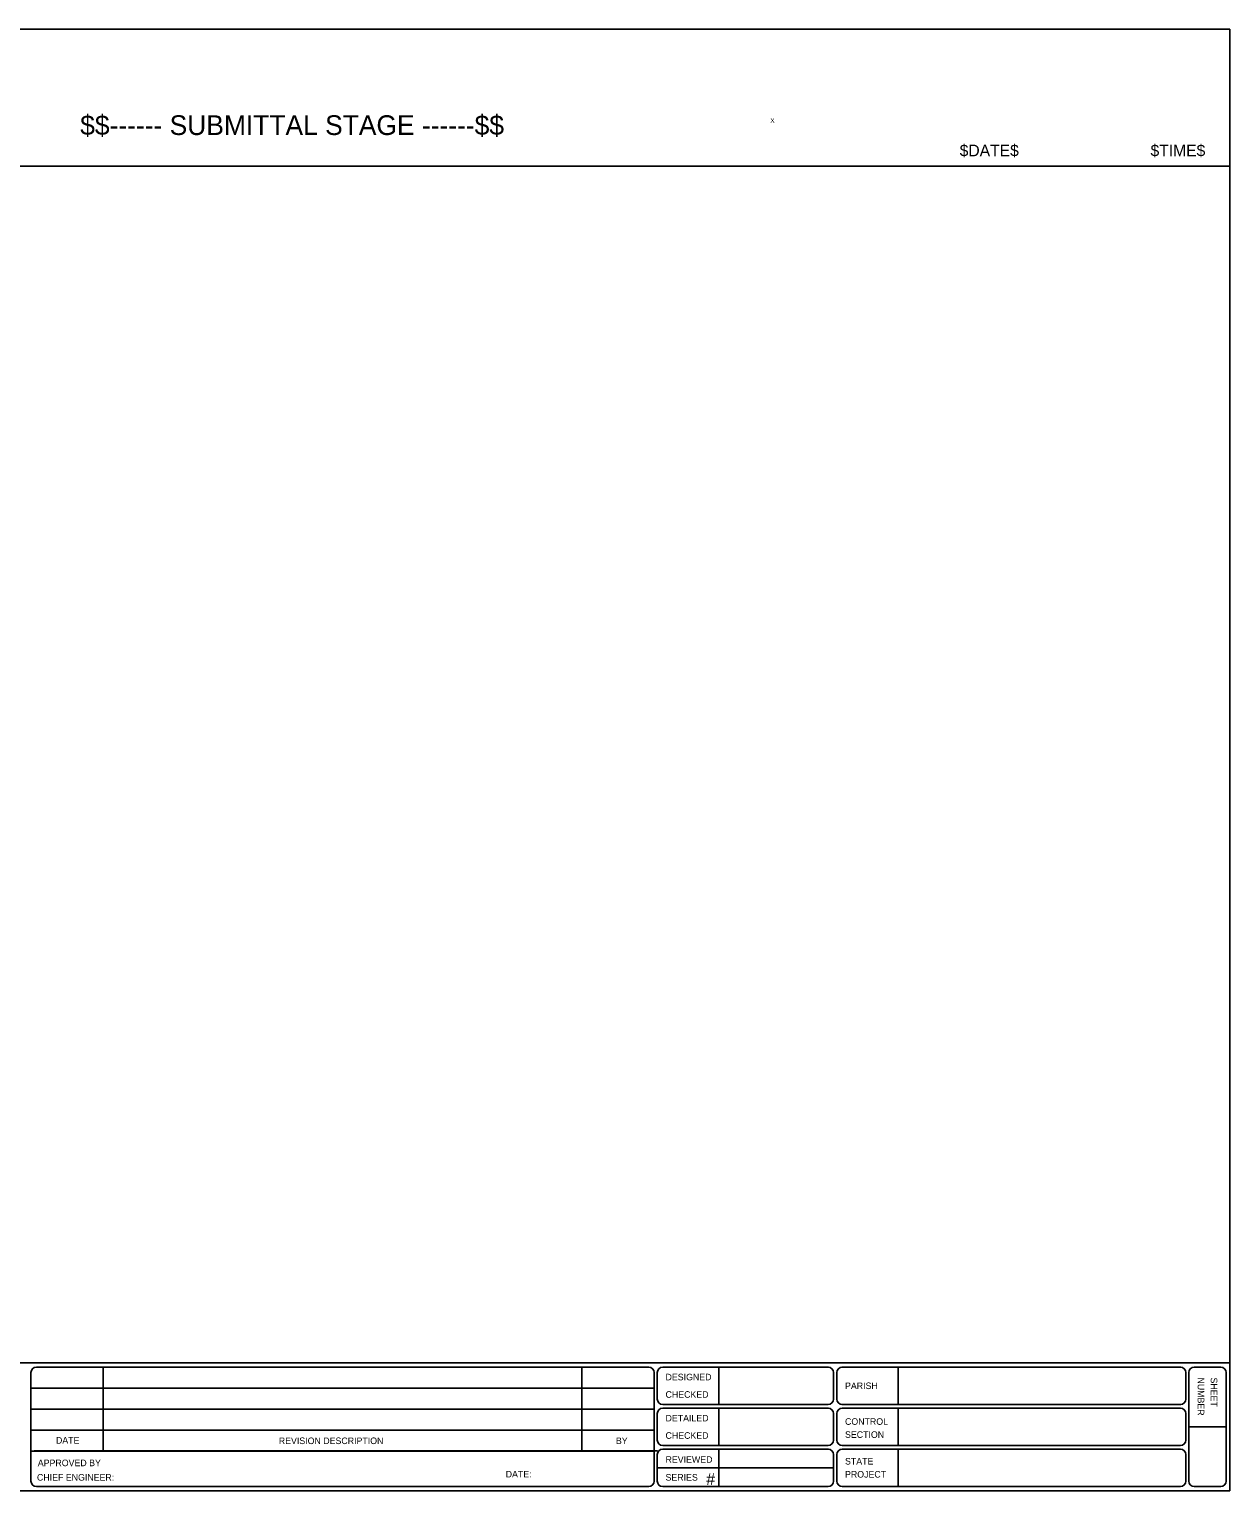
# Model space of a CAD drawing. Extents: x 0 to 21, y 0 to 16.
# Drawn here: x 7.86 to 21, y 0 to 16 of the extents above; entities that cross this region are included whole.
import ezdxf

# ---------------------------------------------------------------- set-up
doc = ezdxf.new("R2010")
doc.units = 0
for name, color, linetype in [('Annotation', 7, 'Continuous'), ('Construction Class', 7, 'Continuous'), ('Plot Border', 7, 'Continuous'), ('Sheet Border', 7, 'Continuous')]:
    doc.layers.add(name, color=color, linetype=linetype)

msp = doc.modelspace()

# ---------------------------------------------------------------- linework, layer by layer
at = {"layer": 'Construction Class'}
msp.add_line((16, 15), (16, 15), dxfattribs=at)
at = {"layer": 'Plot Border'}
msp.add_lwpolyline([(21, 0), (21, 16), (0, 16), (0, 0)], close=True, dxfattribs=at)
at = {"layer": 'Sheet Border'}
for p, q in [((21, 14.5), (0, 14.5)), ((21, 0), (21, 14.5)), ((21, 1.4), (0, 1.4)), ((7.882, 1.294), (7.882, 0.106)), ((14.643, 1.354), (7.941, 1.354)), ((8.674, 0.435), (8.674, 1.354)), ((13.909, 0.435), (13.909, 1.354)), ((14.701, 0.106), (14.701, 1.294)), ((14.736, 1.004), (14.736, 1.294)), ((16.608, 1.354), (14.796, 1.354)), ((15.41, 0.945), (15.41, 1.354)), ((16.663, 1.004), (16.663, 1.294)), ((16.699, 1.004), (16.699, 1.294)), ((20.464, 1.354), (16.754, 1.354)), ((17.373, 0.945), (17.373, 1.354)), ((20.52, 1.004), (20.52, 1.294)), ((20.551, 0.106), (20.551, 1.294)), ((20.901, 1.354), (20.611, 1.354)), ((20.96, 0.106), (20.96, 1.294)), ((14.701, 1.124), (7.882, 1.124)), ((14.701, 0.894), (7.882, 0.894)), ((14.736, 0.554), (14.736, 0.845)), ((16.603, 0.944), (14.796, 0.944)), ((16.608, 0.905), (14.796, 0.905)), ((15.41, 0.495), (15.41, 0.905)), ((16.663, 0.554), (16.663, 0.845)), ((16.699, 0.555), (16.699, 0.846)), ((20.465, 0.945), (16.754, 0.945)), ((20.46, 0.905), (16.759, 0.905)), ((17.373, 0.495), (17.373, 0.905)), ((20.52, 0.555), (20.52, 0.846)), ((14.701, 0.664), (7.882, 0.664)), ((20.96, 0.7), (20.551, 0.7)), ((16.603, 0.495), (14.796, 0.495)), ((20.461, 0.495), (16.758, 0.495)), ((14.701, 0.435), (7.882, 0.435)), ((14.739, 0.437), (7.919, 0.437)), ((14.736, 0.105), (14.736, 0.396)), ((16.608, 0.455), (14.796, 0.455)), ((15.41, 0.046), (15.41, 0.456)), ((16.663, 0.105), (16.663, 0.396)), ((16.699, 0.106), (16.699, 0.396)), ((20.46, 0.456), (16.759, 0.456)), ((17.373, 0.046), (17.373, 0.456)), ((20.52, 0.106), (20.52, 0.396)), ((16.663, 0.251), (14.736, 0.251)), ((21, 0), (0, 0)), ((14.643, 0.046), (7.941, 0.046)), ((16.603, 0.046), (14.796, 0.046)), ((20.46, 0.046), (16.759, 0.046)), ((20.901, 0.046), (20.611, 0.046))]:
    msp.add_line(p, q, dxfattribs=at)
for centre, start, end in [((7.941, 1.294), 90, 180), ((14.643, 1.294), 360, 90), ((14.795, 1.294), 90, 180), ((16.604, 1.294), 360, 90), ((16.759, 1.294), 90, 180), ((20.46, 1.294), 360, 90), ((20.61, 1.294), 90, 180), ((20.901, 1.294), 360, 90), ((14.795, 1.004), 180, 270), ((16.604, 1.004), 270, 360), ((16.759, 1.004), 180, 270), ((20.46, 1.004), 270, 360), ((14.795, 0.845), 90, 180), ((16.604, 0.845), 360, 90), ((16.759, 0.845), 90, 180), ((20.46, 0.845), 360, 90), ((14.795, 0.555), 180, 270), ((16.604, 0.555), 270, 360), ((16.759, 0.555), 180, 270), ((20.46, 0.555), 270, 360), ((14.795, 0.396), 90, 180), ((16.604, 0.396), 360, 90), ((16.759, 0.396), 90, 180), ((20.46, 0.396), 360, 90), ((7.941, 0.106), 180, 270), ((14.643, 0.106), 270, 360), ((14.795, 0.105), 180, 270), ((16.604, 0.105), 270, 360), ((16.759, 0.106), 180, 270), ((20.46, 0.106), 270, 360), ((20.61, 0.106), 180, 270), ((20.901, 0.106), 270, 360)]:
    msp.add_arc(centre, 0.0594, start, end, dxfattribs=at)

# ---------------------------------------------------------------- texts
at = {"layer": 'Annotation'}
msp.add_text('#', height=0.128, rotation=360, dxfattribs=at).set_placement((15.272, 0.063))
at = {"layer": 'Plot Border'}
for s, height, p in [('$$------ SUBMITTAL STAGE ------$$', 0.216, (8.421, 14.842)), ('$DATE$', 0.128, (18.045, 14.609)), ('$TIME$', 0.128, (20.133, 14.609))]:
    msp.add_text(s, height=height, rotation=360, dxfattribs=at).set_placement(p)
at = {"layer": 'Sheet Border'}
msp.add_text('X', height=0.05, dxfattribs=at).set_placement((15.973, 14.975))
for s, rotation, p in [('DESIGNED', 360, (14.826, 1.209)), ('PARISH', 360, (16.79, 1.113)), ('NUMBER', 270, (20.649, 1.24)), ('SHEET', 270, (20.792, 1.24)), ('CHECKED', 360, (14.826, 1.018)), ('DETAILED', 360, (14.826, 0.759)), ('CHECKED', 360, (14.826, 0.569)), ('CONTROL', 360, (16.79, 0.722)), ('SECTION', 360, (16.79, 0.579)), ('DATE', 360, (8.156, 0.516)), ('REVISION DESCRIPTION', 360, (10.594, 0.511)), ('BY', 360, (14.283, 0.511)), ('APPROVED BY', 360, (7.957, 0.269)), ('REVIEWED', 360, (14.826, 0.306)), ('STATE', 360, (16.79, 0.287)), ('CHIEF ENGINEER:', 360, (7.948, 0.111)), ('DATE:', 360, (13.077, 0.146)), ('SERIES', 360, (14.826, 0.111)), ('PROJECT', 360, (16.79, 0.144))]:
    msp.add_text(s, height=0.072, rotation=rotation, dxfattribs=at).set_placement(p)

doc.saveas('drawing.dxf')
